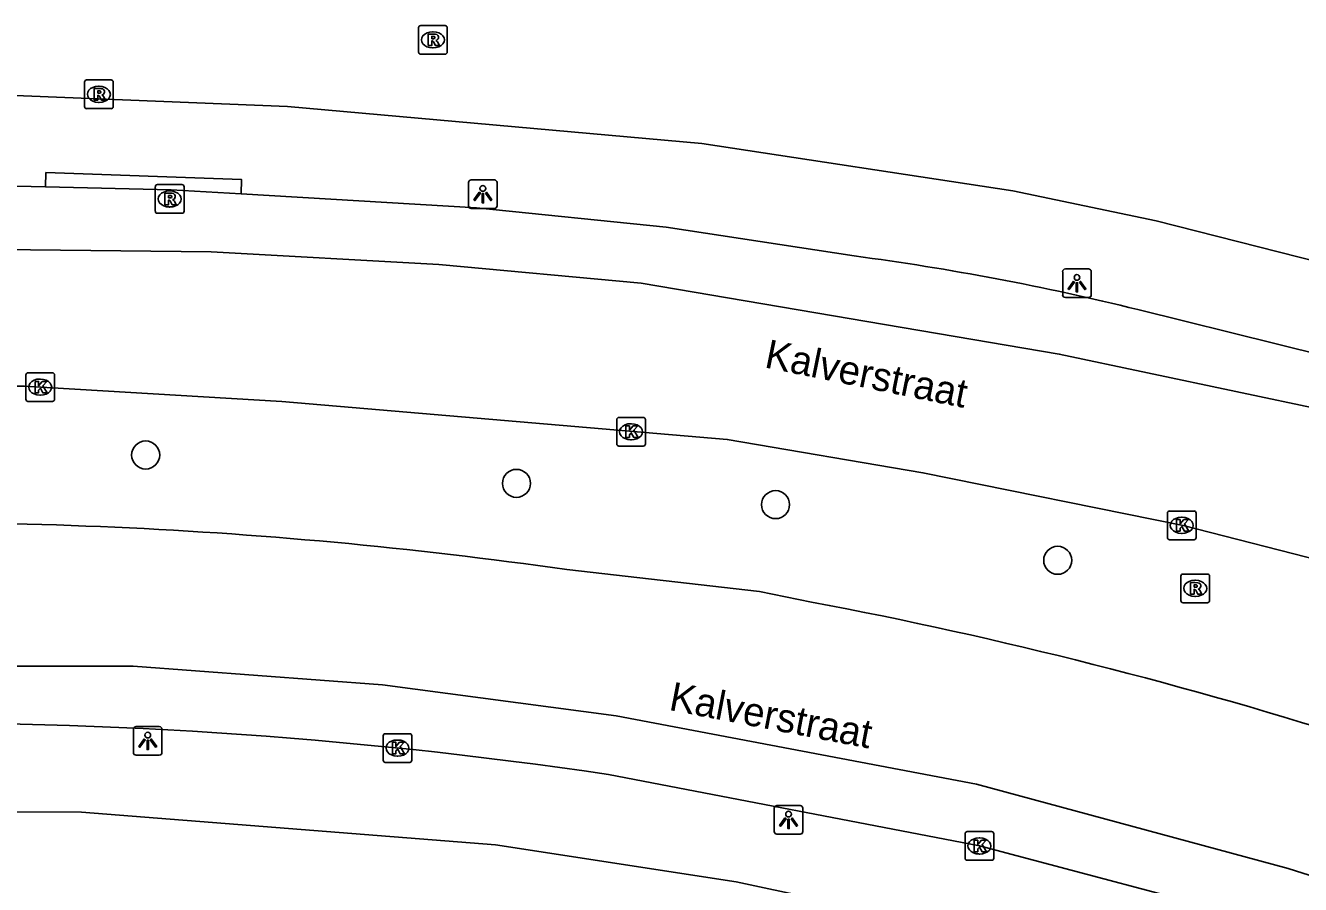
# Model space of a CAD drawing. Extents: x 163010 to 163853, y 382793 to 383982.
# Drawn here: x 163077.85 to 163122.32, y 383910.01 to 383939.96 of the extents above; entities that cross this region are included whole.
import ezdxf

# ---------------------------------------------------------------- set-up
doc = ezdxf.new("R2010")
doc.units = 0
for name, color, linetype in [('IMGEO_Boom', 7, 'Continuous'), ('IMGEO_Kolk', 7, 'Continuous'), ('IMGEO_Lichtpunt', 7, 'Continuous'), ('IMGEO_Openbare_ruimte_label', 7, 'Continuous'), ('IMGEO_Rijbaan_lokaal_gesloten', 7, 'Continuous'), ('IMGEO_Rioolput', 7, 'Continuous'), ('IMGEO_Voetpad_open', 7, 'Continuous')]:
    doc.layers.add(name, color=color, linetype=linetype)

msp = doc.modelspace()

# ---------------------------------------------------------------- linework, layer by layer
at = {"layer": 'IMGEO_Boom'}
for centre in [(163082.039, 383924.98), (163094.973, 383923.992), (163104.01, 383923.25), (163113.851, 383921.309)]:
    msp.add_circle(centre, 0.489, dxfattribs=at)
at = {"layer": 'IMGEO_Kolk'}
for p, q in [((163077.934, 383927.849), (163078.786, 383927.849)), ((163077.859, 383926.923), (163077.859, 383927.775)), ((163078.347, 383927.629), (163078.372, 383927.629)), ((163078.86, 383927.775), (163078.86, 383926.923)), ((163078.37, 383927.069), (163078.345, 383927.069)), ((163078.786, 383926.849), (163077.934, 383926.849)), ((163098.469, 383925.366), (163098.469, 383926.218)), ((163098.544, 383926.292), (163099.396, 383926.292)), ((163098.957, 383926.072), (163098.982, 383926.072)), ((163099.47, 383926.218), (163099.47, 383925.366)), ((163099.396, 383925.292), (163098.544, 383925.292)), ((163098.98, 383925.512), (163098.955, 383925.512)), ((163117.678, 383922.102), (163117.678, 383922.954)), ((163117.753, 383923.028), (163118.605, 383923.028)), ((163118.679, 383922.954), (163118.679, 383922.102)), ((163118.166, 383922.808), (163118.191, 383922.808)), ((163118.605, 383922.028), (163117.753, 383922.028)), ((163118.189, 383922.248), (163118.164, 383922.248)), ((163090.322, 383914.337), (163090.322, 383915.189)), ((163090.397, 383915.263), (163091.249, 383915.263)), ((163090.81, 383915.043), (163090.835, 383915.043)), ((163091.323, 383915.189), (163091.323, 383914.337)), ((163090.833, 383914.483), (163090.808, 383914.483)), ((163091.249, 383914.263), (163090.397, 383914.263)), ((163110.62, 383910.922), (163110.62, 383911.774)), ((163110.695, 383911.848), (163111.547, 383911.848)), ((163111.621, 383911.774), (163111.621, 383910.922)), ((163111.108, 383911.628), (163111.133, 383911.628)), ((163111.131, 383911.068), (163111.106, 383911.068)), ((163111.547, 383910.848), (163110.695, 383910.848))]:
    msp.add_line(p, q, dxfattribs=at)
for points in [[(163077.934, 383927.849), (163078.786, 383927.849)], [(163077.859, 383926.923), (163077.859, 383927.775)], [(163078.18, 383927.549), (163078.303, 383927.549), (163078.303, 383927.398), (163078.433, 383927.549), (163078.597, 383927.549), (163078.451, 383927.398), (163078.604, 383927.149), (163078.452, 383927.149), (163078.367, 383927.313), (163078.303, 383927.246), (163078.303, 383927.149), (163078.18, 383927.149), (163078.18, 383927.549)], [(163078.86, 383927.775), (163078.86, 383926.923)], [(163078.786, 383926.849), (163077.934, 383926.849)], [(163098.469, 383925.366), (163098.469, 383926.218)], [(163098.544, 383926.292), (163099.396, 383926.292)], [(163099.47, 383926.218), (163099.47, 383925.366)], [(163098.79, 383925.992), (163098.913, 383925.992), (163098.913, 383925.841), (163099.043, 383925.992), (163099.207, 383925.992), (163099.061, 383925.841), (163099.214, 383925.592), (163099.062, 383925.592), (163098.977, 383925.756), (163098.913, 383925.689), (163098.913, 383925.592), (163098.79, 383925.592), (163098.79, 383925.992)], [(163099.396, 383925.292), (163098.544, 383925.292)], [(163117.678, 383922.102), (163117.678, 383922.954)], [(163117.753, 383923.028), (163118.605, 383923.028)], [(163118.679, 383922.954), (163118.679, 383922.102)], [(163117.999, 383922.728), (163118.122, 383922.728), (163118.122, 383922.577), (163118.252, 383922.728), (163118.416, 383922.728), (163118.27, 383922.577), (163118.423, 383922.328), (163118.271, 383922.328), (163118.186, 383922.492), (163118.122, 383922.425), (163118.122, 383922.328), (163117.999, 383922.328), (163117.999, 383922.728)], [(163118.605, 383922.028), (163117.753, 383922.028)], [(163090.322, 383914.337), (163090.322, 383915.189)], [(163090.397, 383915.263), (163091.249, 383915.263)], [(163090.643, 383914.963), (163090.766, 383914.963), (163090.766, 383914.812), (163090.896, 383914.963), (163091.06, 383914.963), (163090.914, 383914.812), (163091.067, 383914.563), (163090.915, 383914.563), (163090.83, 383914.727), (163090.766, 383914.66), (163090.766, 383914.563), (163090.643, 383914.563), (163090.643, 383914.963)], [(163091.323, 383915.189), (163091.323, 383914.337)], [(163091.249, 383914.263), (163090.397, 383914.263)], [(163110.62, 383910.922), (163110.62, 383911.774)], [(163110.695, 383911.848), (163111.547, 383911.848)], [(163111.621, 383911.774), (163111.621, 383910.922)], [(163110.941, 383911.548), (163111.064, 383911.548), (163111.064, 383911.397), (163111.194, 383911.548), (163111.358, 383911.548), (163111.212, 383911.397), (163111.365, 383911.148), (163111.213, 383911.148), (163111.128, 383911.312), (163111.064, 383911.245), (163111.064, 383911.148), (163110.941, 383911.148), (163110.941, 383911.548)], [(163111.547, 383910.848), (163110.695, 383910.848)]]:
    msp.add_lwpolyline(points, dxfattribs=at)
for centre, start, end in [((163077.936, 383927.773), 91.552, 178.448), ((163077.936, 383927.773), 91.552, 178.448), ((163078.784, 383927.773), 1.552, 88.448), ((163078.784, 383927.773), 1.552, 88.448), ((163077.936, 383926.925), 181.552, 268.448), ((163077.936, 383926.925), 181.552, 268.448), ((163078.784, 383926.925), 271.552, 358.448), ((163078.784, 383926.925), 271.552, 358.448), ((163098.546, 383926.216), 91.552, 178.448), ((163098.546, 383926.216), 91.552, 178.448), ((163099.394, 383926.216), 1.552, 88.448), ((163099.394, 383926.216), 1.552, 88.448), ((163098.546, 383925.368), 181.552, 268.448), ((163098.546, 383925.368), 181.552, 268.448), ((163099.394, 383925.368), 271.552, 358.448), ((163099.394, 383925.368), 271.552, 358.448), ((163117.755, 383922.952), 91.552, 178.448), ((163117.755, 383922.952), 91.552, 178.448), ((163118.603, 383922.952), 1.552, 88.448), ((163118.603, 383922.952), 1.552, 88.448), ((163117.755, 383922.104), 181.552, 268.448), ((163117.755, 383922.104), 181.552, 268.448), ((163118.603, 383922.104), 271.552, 358.448), ((163118.603, 383922.104), 271.552, 358.448), ((163090.399, 383915.187), 91.552, 178.448), ((163090.399, 383915.187), 91.552, 178.448), ((163091.247, 383915.187), 1.552, 88.448), ((163091.247, 383915.187), 1.552, 88.448), ((163090.399, 383914.339), 181.552, 268.448), ((163090.399, 383914.339), 181.552, 268.448), ((163091.247, 383914.339), 271.552, 358.448), ((163091.247, 383914.339), 271.552, 358.448), ((163110.697, 383911.772), 91.552, 178.448), ((163110.697, 383911.772), 91.552, 178.448), ((163111.545, 383911.772), 1.552, 88.448), ((163111.545, 383911.772), 1.552, 88.448), ((163110.697, 383910.924), 181.552, 268.448), ((163110.697, 383910.924), 181.552, 268.448), ((163111.545, 383910.924), 271.552, 358.448), ((163111.545, 383910.924), 271.552, 358.448)]:
    msp.add_arc(centre, 0.0765, start, end, dxfattribs=at)
for centre, major_axis, ratio, start_param, end_param in [((163078.346, 383927.349), (-0.387, 0.002), 0.722429, 4.712389, 7.853982), ((163078.371, 383927.349), (-0.39, 0.002), 0.717154, 1.570796, 4.712389), ((163098.956, 383925.792), (-0.387, 0.002), 0.722429, 4.712389, 7.853982), ((163098.981, 383925.792), (-0.39, 0.002), 0.717154, 1.570796, 4.712389), ((163118.165, 383922.528), (-0.387, 0.002), 0.722429, 4.712389, 7.853982), ((163118.19, 383922.528), (-0.39, 0.002), 0.717154, 1.570796, 4.712389), ((163090.809, 383914.763), (-0.387, 0.002), 0.722429, 4.712389, 7.853982), ((163090.834, 383914.763), (-0.39, 0.002), 0.717154, 1.570796, 4.712389), ((163111.107, 383911.348), (-0.387, 0.002), 0.722429, 4.712389, 7.853982), ((163111.132, 383911.348), (-0.39, 0.002), 0.717154, 1.570796, 4.712389)]:
    msp.add_ellipse(centre, major_axis=major_axis, ratio=ratio, start_param=start_param, end_param=end_param, dxfattribs=at)
at = {"layer": 'IMGEO_Lichtpunt'}
for p, q in [((163093.301, 383934.478), (163093.301, 383933.671)), ((163093.301, 383934.478), (163093.301, 383933.671)), ((163094.203, 383934.573), (163093.395, 383934.573)), ((163094.203, 383934.573), (163093.395, 383934.573)), ((163094.297, 383933.671), (163094.297, 383934.478)), ((163094.297, 383933.671), (163094.297, 383934.478)), ((163093.395, 383933.577), (163094.203, 383933.577)), ((163093.395, 383933.577), (163094.203, 383933.577)), ((163114.024, 383931.373), (163114.024, 383930.566)), ((163114.024, 383931.373), (163114.024, 383930.566)), ((163114.926, 383931.468), (163114.118, 383931.468)), ((163114.926, 383931.468), (163114.118, 383931.468)), ((163115.02, 383930.566), (163115.02, 383931.373)), ((163115.02, 383930.566), (163115.02, 383931.373)), ((163114.118, 383930.472), (163114.926, 383930.472)), ((163114.118, 383930.472), (163114.926, 383930.472)), ((163081.612, 383915.417), (163081.612, 383914.61)), ((163081.612, 383915.417), (163081.612, 383914.61)), ((163082.514, 383915.512), (163081.706, 383915.512)), ((163082.514, 383915.512), (163081.706, 383915.512)), ((163082.608, 383914.61), (163082.608, 383915.417)), ((163082.608, 383914.61), (163082.608, 383915.417)), ((163081.706, 383914.516), (163082.514, 383914.516)), ((163081.706, 383914.516), (163082.514, 383914.516)), ((163103.964, 383912.662), (163103.964, 383911.855)), ((163103.964, 383912.662), (163103.964, 383911.855)), ((163104.866, 383912.757), (163104.058, 383912.757)), ((163104.866, 383912.757), (163104.058, 383912.757)), ((163104.96, 383911.855), (163104.96, 383912.662)), ((163104.96, 383911.855), (163104.96, 383912.662)), ((163104.058, 383911.761), (163104.866, 383911.761)), ((163104.058, 383911.761), (163104.866, 383911.761))]:
    msp.add_line(p, q, dxfattribs=at)
for points in [[(163093.675, 383934.142), (163093.714, 383934.114), (163093.526, 383933.852), (163093.488, 383933.879), (163093.675, 383934.142)], [(163093.777, 383934.094), (163093.824, 383934.094), (163093.824, 383933.772), (163093.777, 383933.772), (163093.777, 383934.094)], [(163093.887, 383934.114), (163093.925, 383934.141), (163094.112, 383933.879), (163094.073, 383933.851), (163093.887, 383934.114)], [(163114.398, 383931.037), (163114.437, 383931.009), (163114.249, 383930.747), (163114.211, 383930.774), (163114.398, 383931.037)], [(163114.5, 383930.989), (163114.547, 383930.989), (163114.547, 383930.667), (163114.5, 383930.667), (163114.5, 383930.989)], [(163114.61, 383931.009), (163114.648, 383931.036), (163114.835, 383930.774), (163114.796, 383930.746), (163114.61, 383931.009)], [(163081.986, 383915.081), (163082.025, 383915.053), (163081.837, 383914.791), (163081.799, 383914.818), (163081.986, 383915.081)], [(163082.088, 383915.033), (163082.135, 383915.033), (163082.135, 383914.711), (163082.088, 383914.711), (163082.088, 383915.033)], [(163082.198, 383915.053), (163082.236, 383915.08), (163082.423, 383914.818), (163082.384, 383914.79), (163082.198, 383915.053)], [(163104.338, 383912.326), (163104.377, 383912.298), (163104.189, 383912.036), (163104.151, 383912.063), (163104.338, 383912.326)], [(163104.44, 383912.278), (163104.487, 383912.278), (163104.487, 383911.956), (163104.44, 383911.956), (163104.44, 383912.278)], [(163104.55, 383912.298), (163104.588, 383912.325), (163104.775, 383912.063), (163104.736, 383912.035), (163104.55, 383912.298)]]:
    msp.add_lwpolyline(points, dxfattribs=at)
for centre in [(163093.8, 383934.276), (163114.523, 383931.171), (163082.111, 383915.215), (163104.463, 383912.46)]:
    msp.add_circle(centre, 0.0994, dxfattribs=at)
for centre, start, end in [((163093.395, 383934.478), 90, 180), ((163093.395, 383934.478), 90, 180), ((163094.203, 383934.478), 0, 90), ((163094.203, 383934.478), 0, 90), ((163093.395, 383933.671), 180, 270), ((163093.395, 383933.671), 180, 270), ((163094.203, 383933.671), 270, 0), ((163094.203, 383933.671), 270, 360), ((163114.118, 383931.373), 90, 180), ((163114.118, 383931.373), 90, 180), ((163114.926, 383931.373), 0, 90), ((163114.926, 383931.373), 0, 90), ((163114.118, 383930.566), 180, 270), ((163114.118, 383930.566), 180, 270), ((163114.926, 383930.566), 270, 0), ((163114.926, 383930.566), 270, 360), ((163081.706, 383915.417), 90, 180), ((163081.706, 383915.417), 90, 180), ((163082.514, 383915.417), 0, 90), ((163082.514, 383915.417), 0, 90), ((163081.706, 383914.61), 180, 270), ((163081.706, 383914.61), 180, 270), ((163082.514, 383914.61), 270, 0), ((163082.514, 383914.61), 270, 360), ((163104.058, 383912.662), 90, 180), ((163104.058, 383912.662), 90, 180), ((163104.866, 383912.662), 0, 90), ((163104.866, 383912.662), 0, 90), ((163104.058, 383911.855), 180, 270), ((163104.058, 383911.855), 180, 270), ((163104.866, 383911.855), 270, 0), ((163104.866, 383911.855), 270, 360)]:
    msp.add_arc(centre, 0.0946, start, end, dxfattribs=at)
at = {"layer": 'IMGEO_Rijbaan_lokaal_gesloten'}
for points in [[(163078.545, 383934.331), (163071.563, 383934.49), (163061.748, 383934.097), (163049.96, 383933.198), (163048.406, 383933.05)], [(163085.365, 383934.086), (163082.924, 383934.231), (163078.545, 383934.331)], [(163106.753, 383931.923), (163100.189, 383932.926), (163093.583, 383933.597), (163085.365, 383934.086)], [(163049.348, 383930.967), (163053.815, 383931.302), (163058.991, 383931.624), (163066.058, 383931.951), (163074.864, 383932.168), (163084.323, 383932.06), (163092.259, 383931.624), (163099.326, 383930.972), (163113.907, 383928.502), (163123.148, 383926.544), (163132.281, 383923.607), (163144.131, 383919.474), (163175.768, 383906.531), (163199.034, 383896.851), (163211.777, 383892.101), (163220.692, 383889.273), (163232.868, 383886.228), (163246.023, 383883.617), (163247.841, 383883.216)], [(163137.55, 383924.243), (163135.887, 383924.815), (163126.39, 383927.636), (163116.641, 383930.054)], [(163128.117, 383919.856), (163123.488, 383921.171), (163118.231, 383922.517), (163109.152, 383924.363), (163102.323, 383925.525), (163086.786, 383926.85), (163077.814, 383927.382), (163071.788, 383927.384), (163064.331, 383927.156), (163052.705, 383926.424)], [(163096.733, 383920.984), (163103.455, 383920.221), (163105.262, 383919.854)], [(163055.785, 383916.736), (163063.771, 383917.295), (163071.381, 383917.621), (163081.601, 383917.621), (163090.298, 383916.969), (163098.452, 383915.881), (163111.014, 383913.5), (163121.885, 383910.563), (163129.061, 383908.279), (163138.085, 383904.472), (163148.087, 383900.121), (163165.416, 383891.903), (163172.591, 383888.748), (163177.375, 383887.226), (163180.963, 383886.1)], [(163121.111, 383908.706), (163111.125, 383911.348), (163098.183, 383913.84)]]:
    msp.add_lwpolyline(points, dxfattribs=at)
for centre, radius, start, end in [((163094.791, 383841.545), 91.166, 76.13258, 82.46022), ((163073.542, 383758.414), 164.216, 81.88159, 93.29041), ((163074.668, 383758.32), 164.406, 72.26112, 79.27537), ((163073.776, 383749.236), 166.404, 81.5658, 91.02576), ((162162.76, 383521.49), 971.787, 16.429932, 23.585119)]:
    msp.add_arc(centre, radius, start, end, dxfattribs=at)
at = {"layer": 'IMGEO_Rioolput'}
for p, q in [((163091.558, 383939.03), (163091.558, 383939.882)), ((163091.633, 383939.956), (163092.485, 383939.956)), ((163092.559, 383939.882), (163092.559, 383939.03)), ((163092.046, 383939.736), (163092.071, 383939.736)), ((163092.485, 383938.956), (163091.633, 383938.956)), ((163092.069, 383939.176), (163092.044, 383939.176)), ((163079.98, 383938.057), (163080.832, 383938.057)), ((163079.905, 383937.131), (163079.905, 383937.983)), ((163080.393, 383937.837), (163080.418, 383937.837)), ((163080.906, 383937.983), (163080.906, 383937.131)), ((163080.416, 383937.277), (163080.391, 383937.277)), ((163080.832, 383937.057), (163079.98, 383937.057)), ((163082.376, 383933.482), (163082.376, 383934.334)), ((163082.451, 383934.408), (163083.303, 383934.408)), ((163082.864, 383934.188), (163082.889, 383934.188)), ((163083.377, 383934.334), (163083.377, 383933.482)), ((163082.887, 383933.628), (163082.862, 383933.628)), ((163083.303, 383933.408), (163082.451, 383933.408)), ((163118.147, 383919.905), (163118.147, 383920.757)), ((163118.222, 383920.831), (163119.074, 383920.831)), ((163119.148, 383920.757), (163119.148, 383919.905)), ((163118.635, 383920.611), (163118.66, 383920.611)), ((163119.074, 383919.831), (163118.222, 383919.831)), ((163118.658, 383920.051), (163118.633, 383920.051))]:
    msp.add_line(p, q, dxfattribs=at)
for points in [[(163091.558, 383939.03), (163091.558, 383939.882)], [(163091.633, 383939.956), (163092.485, 383939.956)], [(163092.559, 383939.882), (163092.559, 383939.03)], [(163092.147, 383939.654), (163091.895, 383939.656), (163091.895, 383939.256)], [(163091.895, 383939.256), (163092.019, 383939.256), (163092.019, 383939.418), (163092.03, 383939.418)], [(163092.073, 383939.575), (163092.019, 383939.575), (163092.019, 383939.494)], [(163092.019, 383939.494), (163092.071, 383939.494)], [(163092.077, 383939.389), (163092.148, 383939.256), (163092.288, 383939.256), (163092.223, 383939.382)], [(163092.485, 383938.956), (163091.633, 383938.956)], [(163079.98, 383938.057), (163080.832, 383938.057)], [(163079.905, 383937.131), (163079.905, 383937.983)], [(163080.494, 383937.755), (163080.242, 383937.757), (163080.242, 383937.357)], [(163080.42, 383937.676), (163080.366, 383937.676), (163080.366, 383937.595)], [(163080.366, 383937.595), (163080.418, 383937.595)], [(163080.906, 383937.983), (163080.906, 383937.131)], [(163080.242, 383937.357), (163080.366, 383937.357), (163080.366, 383937.519), (163080.377, 383937.519)], [(163080.424, 383937.49), (163080.495, 383937.357), (163080.635, 383937.357), (163080.57, 383937.483)], [(163080.832, 383937.057), (163079.98, 383937.057)], [(163082.376, 383933.482), (163082.376, 383934.334)], [(163082.451, 383934.408), (163083.303, 383934.408)], [(163082.965, 383934.106), (163082.713, 383934.108), (163082.713, 383933.708)], [(163082.891, 383934.027), (163082.837, 383934.027), (163082.837, 383933.946)], [(163083.377, 383934.334), (163083.377, 383933.482)], [(163082.713, 383933.708), (163082.837, 383933.708), (163082.837, 383933.87), (163082.848, 383933.87)], [(163082.837, 383933.946), (163082.889, 383933.946)], [(163082.895, 383933.841), (163082.966, 383933.708), (163083.106, 383933.708), (163083.041, 383933.834)], [(163083.303, 383933.408), (163082.451, 383933.408)], [(163118.147, 383919.905), (163118.147, 383920.757)], [(163118.222, 383920.831), (163119.074, 383920.831)], [(163119.148, 383920.757), (163119.148, 383919.905)], [(163118.736, 383920.529), (163118.484, 383920.531), (163118.484, 383920.131)], [(163118.484, 383920.131), (163118.608, 383920.131), (163118.608, 383920.293), (163118.619, 383920.293)], [(163118.662, 383920.45), (163118.608, 383920.45), (163118.608, 383920.369)], [(163118.608, 383920.369), (163118.66, 383920.369)], [(163118.666, 383920.264), (163118.737, 383920.131), (163118.877, 383920.131), (163118.812, 383920.257)], [(163119.074, 383919.831), (163118.222, 383919.831)]]:
    msp.add_lwpolyline(points, dxfattribs=at)
for centre, radius, start, end in [((163091.635, 383939.88), 0.0765, 91.552, 178.448), ((163091.635, 383939.88), 0.0765, 91.552, 178.448), ((163092.483, 383939.88), 0.0765, 1.552, 88.448), ((163092.483, 383939.88), 0.0765, 1.552, 88.448), ((163092.029, 383939.365), 0.0533, 26.0293, 88.6989), ((163092.055, 383939.683), 0.19, 274.7715, 282.9687), ((163092.079, 383939.479), 0.0964, 77.0061, 93.1865), ((163092.093, 383939.536), 0.0378, 276.6634, 79.6772), ((163092.146, 383939.544), 0.109, 350.3612, 89.416), ((163092.144, 383939.544), 0.112, 277.5842, 350.9817), ((163092.128, 383939.329), 0.108, 29.5134, 73.7905), ((163091.635, 383939.032), 0.0765, 181.552, 268.448), ((163091.635, 383939.032), 0.0765, 181.552, 268.448), ((163092.483, 383939.032), 0.0765, 271.552, 358.448), ((163092.483, 383939.032), 0.0765, 271.552, 358.448), ((163079.982, 383937.981), 0.0765, 91.552, 178.448), ((163079.982, 383937.981), 0.0765, 91.552, 178.448), ((163080.83, 383937.981), 0.0765, 1.552, 88.448), ((163080.83, 383937.981), 0.0765, 1.552, 88.448), ((163080.402, 383937.784), 0.19, 274.7715, 282.9687), ((163080.426, 383937.58), 0.0964, 77.0061, 93.1865), ((163080.44, 383937.637), 0.0378, 276.6634, 79.6772), ((163080.493, 383937.645), 0.109, 350.3612, 89.416), ((163080.491, 383937.645), 0.112, 277.5842, 350.9817), ((163079.982, 383937.133), 0.0765, 181.552, 268.448), ((163079.982, 383937.133), 0.0765, 181.552, 268.448), ((163080.376, 383937.466), 0.0533, 26.0293, 88.6989), ((163080.475, 383937.43), 0.108, 29.5134, 73.7905), ((163080.83, 383937.133), 0.0765, 271.552, 358.448), ((163080.83, 383937.133), 0.0765, 271.552, 358.448), ((163082.453, 383934.332), 0.0765, 91.552, 178.448), ((163082.453, 383934.332), 0.0765, 91.552, 178.448), ((163082.897, 383933.931), 0.0964, 77.0061, 93.1865), ((163082.911, 383933.988), 0.0378, 276.6634, 79.6772), ((163082.964, 383933.996), 0.109, 350.3612, 89.416), ((163083.301, 383934.332), 0.0765, 1.552, 88.448), ((163083.301, 383934.332), 0.0765, 1.552, 88.448), ((163082.847, 383933.817), 0.0533, 26.0293, 88.6989), ((163082.873, 383934.135), 0.19, 274.7715, 282.9687), ((163082.962, 383933.996), 0.112, 277.5842, 350.9817), ((163082.946, 383933.781), 0.108, 29.5134, 73.7905), ((163082.453, 383933.484), 0.0765, 181.552, 268.448), ((163082.453, 383933.484), 0.0765, 181.552, 268.448), ((163083.301, 383933.484), 0.0765, 271.552, 358.448), ((163083.301, 383933.484), 0.0765, 271.552, 358.448), ((163118.224, 383920.755), 0.0765, 91.552, 178.448), ((163118.224, 383920.755), 0.0765, 91.552, 178.448), ((163119.072, 383920.755), 0.0765, 1.552, 88.448), ((163119.072, 383920.755), 0.0765, 1.552, 88.448), ((163118.618, 383920.24), 0.0533, 26.0293, 88.6989), ((163118.644, 383920.558), 0.19, 274.7715, 282.9687), ((163118.668, 383920.354), 0.0964, 77.0061, 93.1865), ((163118.682, 383920.411), 0.0378, 276.6634, 79.6772), ((163118.735, 383920.419), 0.109, 350.3612, 89.416), ((163118.733, 383920.419), 0.112, 277.5842, 350.9817), ((163118.717, 383920.204), 0.108, 29.5134, 73.7905), ((163118.224, 383919.907), 0.0765, 181.552, 268.448), ((163118.224, 383919.907), 0.0765, 181.552, 268.448), ((163119.072, 383919.907), 0.0765, 271.552, 358.448), ((163119.072, 383919.907), 0.0765, 271.552, 358.448)]:
    msp.add_arc(centre, radius, start, end, dxfattribs=at)
for centre, major_axis, ratio, start_param, end_param in [((163092.045, 383939.456), (-0.387, 0.002), 0.722429, 4.712389, 7.853982), ((163092.07, 383939.456), (-0.39, 0.002), 0.717154, 1.570796, 4.712389), ((163080.392, 383937.557), (-0.387, 0.002), 0.722429, 4.712389, 7.853982), ((163080.417, 383937.557), (-0.39, 0.002), 0.717154, 1.570796, 4.712389), ((163082.863, 383933.908), (-0.387, 0.002), 0.722429, 4.712389, 7.853982), ((163082.888, 383933.908), (-0.39, 0.002), 0.717154, 1.570796, 4.712389), ((163118.634, 383920.331), (-0.387, 0.002), 0.722429, 4.712389, 7.853982), ((163118.659, 383920.331), (-0.39, 0.002), 0.717154, 1.570796, 4.712389)]:
    msp.add_ellipse(centre, major_axis=major_axis, ratio=ratio, start_param=start_param, end_param=end_param, dxfattribs=at)
at = {"layer": 'IMGEO_Voetpad_open'}
for points in [[(163053.933, 383937.027), (163053.953, 383936.658), (163066.661, 383937.409), (163076.906, 383937.538), (163086.987, 383937.137), (163101.44, 383935.846), (163112.282, 383934.196), (163117.29, 383933.145), (163127.258, 383930.613), (163137, 383927.725), (163146.563, 383924.32), (163155.953, 383920.628), (163176.923, 383911.904)], [(163078.545, 383934.331), (163078.562, 383934.83), (163085.382, 383934.585), (163085.365, 383934.086)], [(163149.242, 383893.99), (163139.151, 383898.874), (163129.822, 383902.595), (163125.01, 383904.299), (163120.135, 383905.812), (163110.459, 383908.428), (163102.636, 383910.097), (163094.243, 383911.389), (163079.804, 383912.529), (163067.557, 383912.546), (163075.735, 383899.671)]]:
    msp.add_lwpolyline(points, dxfattribs=at)

# ---------------------------------------------------------------- texts
at = {"layer": 'IMGEO_Openbare_ruimte_label'}
for rotation, p in [(348.5215, (163103.589, 383928.041)), (349.1058, (163100.256, 383916.096))]:
    msp.add_text('Kalverstraat', height=1, rotation=rotation, dxfattribs=at).set_placement(p)

doc.saveas('drawing.dxf')
